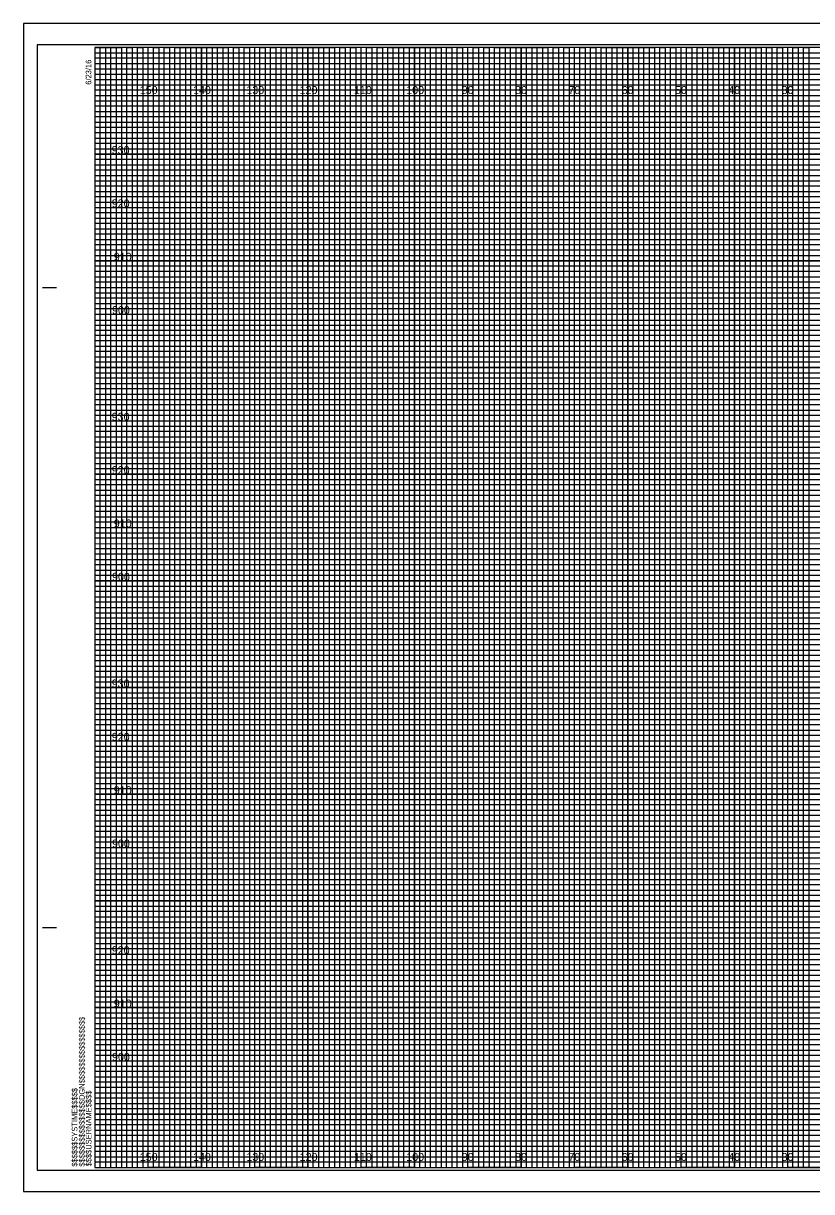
# Model space of a CAD drawing. Extents: x -13 to 323, y -4 to 3074.
# Drawn here: x -13.4 to 134.5, y -4.5 to 214.5 of the extents above; entities that cross this region are included whole.
import ezdxf

# ---------------------------------------------------------------- set-up
doc = ezdxf.new("R2010")
doc.units = 0
for name, color, linetype in [('Prop XS Elevation Labels', 7, 'Continuous'), ('Prop XS Offset Labels', 7, 'Continuous'), ('Sheet Cross Section CELL', 7, 'Continuous'), ('Sheet Cross Section Grid Major CELL', 7, 'Continuous'), ('Sheet Cross Section Grid Middle CELL', 7, 'Continuous'), ('Sheet Cross Section Grid Minor 1 CELL', 7, 'Continuous'), ('Sheet Cross Section Grid Minor 2 CELL', 7, 'Continuous'), ('Sheet Cutting Line CELL', 7, 'Continuous'), ('Sheet DOT Grid CELL', 7, 'Continuous'), ('Sheet Plot Border Inside CELL', 7, 'Continuous'), ('Sheet Plot Border Outside CELL', 7, 'Continuous')]:
    doc.layers.add(name, color=color, linetype=linetype)

msp = doc.modelspace()

# ---------------------------------------------------------------- linework, layer by layer
at = {"layer": 'Sheet Cross Section CELL'}
for p, q in [((-9.8, 165), (-7.3, 165)), ((-9.7, 165), (-7.2, 165)), ((-9.8, 45), (-7.3, 45)), ((-9.7, 45), (-7.2, 45)), ((0, 0), (0, 0)), ((0, 0), (0, 0)), ((0, 0), (0, 0)), ((0, 0), (0, 0)), ((0, 0), (0, 0)), ((0, 0), (0, 0)), ((0, 0), (0, 0))]:
    msp.add_line(p, q, dxfattribs=at)
msp.add_lwpolyline([(320, 210), (0, 210), (0, 0), (320, 0)], close=True, dxfattribs=at)
at = {"layer": 'Sheet Cross Section Grid Major CELL'}
for p, q in [((10, 210), (0, 210)), ((10, 0), (10, 210)), ((30, 210), (20, 210)), ((20, 210), (20, 0)), ((30, 0), (30, 210)), ((50, 210), (40, 210)), ((40, 210), (40, 0)), ((50, 0), (50, 210)), ((70, 210), (60, 210)), ((60, 210), (60, 0)), ((70, 0), (70, 210)), ((90, 210), (80, 210)), ((80, 210), (80, 0)), ((90, 0), (90, 210)), ((110, 210), (100, 210)), ((100, 210), (100, 0)), ((110, 0), (110, 210)), ((130, 210), (120, 210)), ((120, 210), (120, 0)), ((130, 0), (130, 210)), ((20, 0), (10, 0)), ((40, 0), (30, 0)), ((60, 0), (50, 0)), ((80, 0), (70, 0)), ((100, 0), (90, 0)), ((120, 0), (110, 0)), ((140, 0), (130, 0))]:
    msp.add_line(p, q, dxfattribs=at)
for points in [[(0, 200), (320, 200), (320, 190), (0, 190)], [(0, 180), (320, 180), (320, 170), (0, 170)], [(0, 160), (320, 160), (320, 150), (0, 150)], [(0, 140), (320, 140), (320, 130), (0, 130)], [(0, 120), (320, 120), (320, 110), (0, 110)], [(0, 100), (320, 100), (320, 90), (0, 90)], [(0, 80), (320, 80), (320, 70), (0, 70)], [(0, 60), (320, 60), (320, 50), (0, 50)], [(0, 40), (320, 40), (320, 30), (0, 30)], [(0, 20), (320, 20), (320, 10), (0, 10)]]:
    msp.add_lwpolyline(points, dxfattribs=at)
at = {"layer": 'Sheet Cross Section Grid Middle CELL'}
for points in [[(0, 210), (5, 210), (5, 0), (15, 0), (15, 210), (25, 210), (25, 0), (35, 0), (35, 210), (45, 210), (45, 0), (55, 0), (55, 210), (65, 210), (65, 0), (75, 0), (75, 210), (85, 210), (85, 0), (95, 0), (95, 210), (105, 210), (105, 0), (115, 0), (115, 210), (125, 210), (125, 0), (135, 0)], [(0, 205), (275, 205)], [(0, 185), (320, 185), (320, 195), (0, 195)], [(0, 165), (320, 165), (320, 175), (0, 175)], [(0, 145), (320, 145), (320, 155), (0, 155)], [(0, 125), (320, 125), (320, 135), (0, 135)], [(0, 105), (320, 105), (320, 115), (0, 115)], [(0, 85), (320, 85), (320, 95), (0, 95)], [(0, 65), (320, 65), (320, 75), (0, 75)], [(0, 45), (320, 45), (320, 55), (0, 55)], [(0, 25), (320, 25), (320, 35), (0, 35)], [(0, 5), (320, 5), (320, 15), (0, 15)]]:
    msp.add_lwpolyline(points, dxfattribs=at)
at = {"layer": 'Sheet Cross Section Grid Minor 1 CELL'}
for p, q in [((0, 209), (260, 209)), ((260, 207.98), (0, 207.98)), ((0, 207.98), (0, 207)), ((0, 207), (260, 207)), ((260, 205.89), (0, 205.89)), ((0, 205.89), (0, 204)), ((0, 204), (320, 204))]:
    msp.add_line(p, q, dxfattribs=at)
for points in [[(0, 203), (270, 203), (320, 203), (320, 202), (0, 202)], [(0, 201), (320, 201), (320, 199), (0, 199)], [(0, 198), (320, 198), (320, 197), (0, 196.98)], [(0, 196), (320, 196), (320, 194), (0, 194)], [(0, 193), (320, 193), (320, 192), (0, 192)], [(0, 191), (320, 191), (320, 189), (0, 189)], [(0, 188), (320, 188), (320, 187), (0, 187)], [(0, 186), (320, 186), (320, 184), (0, 184)], [(0, 183), (320, 183), (320, 182), (0, 182)], [(0, 181), (320, 181), (320, 179), (0, 179)], [(0, 178), (320, 178), (320, 177), (0, 177)], [(0, 176), (320, 176), (320, 173.95), (320, 173), (320, 172), (0, 172)], [(0, 174), (320, 174), (320, 173), (0, 173)], [(0, 171), (320, 171), (320, 169), (0, 169.03)], [(0, 169.03), (320, 169), (320, 168), (0, 168)], [(0, 167), (320, 167), (320, 166), (0, 166)], [(0, 164), (320, 164), (320, 163), (0, 163)], [(0, 162), (320, 162), (320, 161), (0, 161)], [(-0.07, 158.89), (320, 158.89), (320, 157.88), (-0.07, 157.88)], [(0, 157), (320, 157), (320, 156), (0, 156)], [(0, 154), (320, 154), (320, 153), (0, 153)], [(0, 152), (320, 152), (320, 151), (0, 151)], [(0, 149), (320, 149), (320, 148), (0, 148)], [(0, 147), (320, 147), (320, 146), (0, 146)], [(0, 144), (320, 144), (320, 143), (0, 143)], [(0, 142), (320, 142), (320, 141), (0, 141)], [(0, 139), (320, 139), (319.99, 137.98), (0, 138)], [(0, 137), (320, 137), (320, 136), (0, 136)], [(0, 134), (320, 134), (320, 133), (0, 133)], [(0, 132), (320, 132), (320, 131), (0, 131)], [(0, 129), (320, 129), (320, 128), (0, 128)], [(0, 127), (320, 127), (320, 126), (0, 126)], [(0, 124), (320, 124), (320, 123), (0, 123)], [(0, 122), (320, 122), (320, 121), (0, 121)], [(0, 119), (320, 119), (320, 118), (0, 118)], [(0, 116.99), (320.07, 116.91), (320, 116), (0, 116)], [(0, 114), (320, 114), (320, 113), (0, 113)], [(0, 112), (320, 112), (320, 111), (0, 111)], [(0, 109), (320, 109), (320, 108), (0, 108)], [(0, 107), (320, 107), (320, 106), (0, 106)], [(0, 104), (320, 104), (320, 103), (0, 103)], [(0, 102), (320, 102), (320, 101), (0, 101)], [(0, 99), (320, 99), (320, 98), (0, 98)], [(0, 97), (320, 97), (320, 96), (0, 96)], [(0, 94), (320, 94), (320, 93), (0, 93)], [(0, 92), (320, 92), (320, 91), (0, 91)], [(0, 89), (320, 89), (320, 88), (0, 88)], [(0, 87), (320, 87), (320, 86), (0, 86)], [(0, 84), (320, 84), (320, 83), (0, 83)], [(0, 82), (320, 82), (320, 81), (0, 81)], [(0, 79), (320, 79), (319.99, 77.98), (0, 78)], [(0, 77), (320, 77), (320, 76), (0, 76)], [(0, 74), (320, 74), (320, 73), (0, 73)], [(0, 72), (320, 72), (320, 71), (0, 71)], [(0, 69), (320, 69), (320, 68), (0, 68)], [(0, 67), (320, 67), (320, 66), (0, 66)], [(0, 64), (320, 64), (320, 63), (0, 63)], [(0, 62), (320, 62), (320, 61), (0, 61)], [(0, 59), (320, 59), (320, 58), (0, 58)], [(0, 56.99), (320.07, 56.91), (320, 56), (0, 56)], [(0, 54), (320, 54), (320, 53), (0, 53)], [(0, 52), (320, 52), (320, 51), (0, 51)], [(0, 49), (320, 49), (320, 48), (0, 48)], [(0, 47), (320, 47), (320, 46), (0, 46)], [(0, 44), (320, 44), (320, 43), (0, 43)], [(0, 42), (320, 42), (320, 41), (0, 41)], [(0, 39), (320, 39), (320, 38), (0, 38)], [(0, 37), (320, 37), (320, 36), (0, 36)], [(0, 34), (320, 34), (320, 33), (0, 33)], [(0, 32), (320, 32), (320, 31), (0, 31)], [(0, 29), (320, 29), (320, 28), (0, 28)], [(0, 27), (320, 27), (320, 26), (0, 26)], [(0, 24), (320, 24), (320, 23), (0, 23)], [(0, 22), (320, 22), (320, 21), (0, 21)], [(0, 19), (320, 19), (320, 18), (0, 18)], [(0, 17), (320, 17), (320, 16), (0, 16)], [(0, 14), (320, 14), (320, 13), (0, 13)], [(0, 12), (320, 12), (320, 11), (0, 11)], [(0, 9), (320, 9), (320, 8), (0, 8)], [(0, 7), (320, 7), (320, 6), (0, 6)], [(0, 4), (320, 4), (320, 3), (0, 3)], [(0, 2), (320, 2), (320, 1), (0, 1)]]:
    msp.add_lwpolyline(points, dxfattribs=at)
at = {"layer": 'Sheet Cross Section Grid Minor 2 CELL'}
for points in [[(0, 0), (1, 0), (1, 210), (2, 210), (2, 0)], [(2, 0), (3, 0), (3, 210), (4, 210), (4, 0)], [(5, 0), (6, 0), (6, 210), (7, 210), (7, 0)], [(7, 0), (8, 0), (8, 210), (9, 210), (9, 0)], [(10, 0), (11, 0), (11, 210), (12, 210), (12, 0)], [(12, 0), (13, 0), (13, 210), (14, 210), (14, 0)], [(15, 0), (16, 0), (16, 210), (17, 210), (17, 0)], [(17, 0), (18, 0), (18, 210), (19, 210), (19, 0)], [(20, 0), (21, 0), (21, 210), (22, 210), (22, 0)], [(22, 0), (23, 0), (23, 210), (24, 210), (24, 0)], [(25, 0), (26, 0), (26, 210), (27, 210), (27, 0)], [(27, 0), (28, 0), (28, 210), (29, 210), (29, 0)], [(30, 0), (31, 0), (31, 210), (32, 210), (32, 0)], [(32, 0), (33, 0), (33, 210), (34, 210), (34, 0)], [(35, 0), (36, 0), (36, 210), (37, 210), (37, 0)], [(37, 0), (38, 0), (38, 210), (39, 210), (39, 0)], [(40, 0), (41, 0), (41, 210), (42, 210), (42, 0)], [(42, 0), (43, 0), (43, 210), (44, 210), (44, 0)], [(45, 0), (46, 0), (46, 210), (47, 210), (47, 0)], [(47, 0), (48, 0), (48, 210), (49, 210), (49, 0)], [(50, 0), (51, 0), (51, 210), (52, 210), (52, 0)], [(52, 0), (53, 0), (53, 210), (54, 210), (54, 0)], [(55, 0), (56, 0), (56, 210), (57, 210), (57, 0)], [(57, 0), (58, 0), (58, 210), (59, 210), (59, 0)], [(60, 0), (61, 0), (61, 210), (62, 210), (62, 0)], [(62, 0), (63, 0), (63, 210), (64, 210), (64, 0)], [(65, 0), (66, 0), (66, 210), (67, 210), (67, 0)], [(67, 0), (68, 0), (68, 210), (69, 210), (69, 0)], [(70, 0), (71, 0), (71, 210), (72, 210), (72, 0)], [(72, 0), (73, 0), (73, 210), (74, 210), (74, 0)], [(75, 0), (76, 0), (76, 210), (77, 210), (77, 0)], [(77, 0), (78, 0), (78, 210), (79, 210), (79, 0)], [(80, 0), (81, 0), (81, 210), (82, 210), (82, 0)], [(82, 0), (83, 0), (83, 210), (84, 210), (84, 0)], [(85, 0), (86, 0), (86, 210), (87, 210), (87, 0)], [(87, 0), (88, 0), (88, 210), (89, 210), (89, 0)], [(90, 0), (91, 0), (91, 210), (92, 210), (92, 0)], [(92, 0), (93, 0), (93, 210), (94, 210), (94, 0)], [(95, 0), (96, 0), (96, 210), (97, 210), (97, 0)], [(97, 0), (98, 0), (98, 210), (99, 210), (99, 0)], [(100, 0), (101, 0), (101, 210), (102, 210), (102, 0)], [(102, 0), (103, 0), (103, 210), (104, 210), (104, 0)], [(105, 0), (106, 0), (106, 210), (107, 210), (107, 0)], [(107, 0), (108, 0), (108, 210), (109, 210), (109, 0)], [(110, 0), (111, 0), (111, 210), (112, 210), (112, 0)], [(112, 0), (113, 0), (113, 210), (114, 210), (114, 0)], [(115, 0), (116, 0), (116, 210), (117, 210), (117, 0)], [(117, 0), (118, 0), (118, 210), (119, 210), (119, 0)], [(120, 0), (121, 0), (121, 210), (122, 210), (122, 0)], [(122, 0), (123, 0), (123, 210), (124, 210), (124, 0)], [(125, 0), (126, 0), (126, 210), (127, 210), (127, 0)], [(127, 0), (128, 0), (128, 210), (129, 210), (129, 0)], [(130, 0), (131, 0), (131, 210), (132, 210), (132, 0)], [(132, 0), (133, 0), (133, 210), (134, 210), (134, 0)]]:
    msp.add_lwpolyline(points, dxfattribs=at)
at = {"layer": 'Sheet Cutting Line CELL'}
for p, q in [((323.3, 214.5), (-13.4, 214.5)), ((-13.4, 214.5), (-13.4, -4.5)), ((-13.4, -4.5), (323.3, -4.5))]:
    msp.add_line(p, q, dxfattribs=at)
at = {"layer": 'Sheet DOT Grid CELL'}
for p, q in [((10, 0), (10, 210)), ((20, 0), (20, 210)), ((30, 0), (30, 210)), ((40, 0), (40, 210)), ((50, 0), (50, 210)), ((60, 0), (60, 210)), ((70, 0), (70, 210)), ((80, 0), (80, 210)), ((90, 0), (90, 210)), ((100, 0), (100, 210)), ((110, 0), (110, 210)), ((120, 0), (120, 210)), ((130, 0), (130, 210)), ((0, 200), (320, 200)), ((0, 190), (320, 190)), ((0, 180), (320, 180)), ((0, 170), (320, 170)), ((0, 160), (320, 160)), ((0, 150), (320, 150)), ((0, 140), (320, 140)), ((0, 130), (320, 130)), ((0, 120), (320, 120)), ((0, 110), (320, 110)), ((0, 100), (320, 100)), ((0, 90), (320, 90)), ((0, 80), (320, 80)), ((0, 70), (320, 70)), ((0, 60), (320, 60)), ((0, 50), (320, 50)), ((0, 40), (320, 40)), ((0, 30), (320, 30)), ((0, 20), (320, 20)), ((0, 10), (320, 10))]:
    msp.add_line(p, q, dxfattribs=at)
at = {"layer": 'Sheet Plot Border Inside CELL'}
msp.add_lwpolyline([(-10.8, -0.5), (322.4, -0.5), (322.4, 210.5), (-10.8, 210.5)], close=True, dxfattribs=at)
at = {"layer": 'Sheet Plot Border Outside CELL'}
msp.add_lwpolyline([(-13.4, -4.5), (323.3, -4.5), (323.3, 214.5), (-13.4, 214.5)], close=True, dxfattribs=at)

# ---------------------------------------------------------------- texts
at = {"layer": 'Prop XS Elevation Labels'}
for s, p in [('930', (3.18, 190)), ('920', (3.19, 180)), ('910', (3.57, 170)), ('900', (3.24, 160)), ('930', (3.18, 140)), ('920', (3.19, 130)), ('910', (3.57, 120)), ('900', (3.24, 110)), ('930', (3.18, 90)), ('920', (3.19, 80)), ('910', (3.57, 70)), ('900', (3.24, 60)), ('920', (3.19, 40)), ('910', (3.57, 30)), ('900', (3.24, 20))]:
    msp.add_text(s, height=1.5, dxfattribs=at).set_placement(p)
at = {"layer": 'Prop XS Offset Labels'}
for s, p in [('150', (8.44, 201.25)), ('140', (18.44, 201.25)), ('130', (28.44, 201.25)), ('120', (38.44, 201.25)), ('110', (48.62, 201.25)), ('100', (58.44, 201.25)), ('90', (68.86, 201.25)), ('80', (78.86, 201.25)), ('70', (88.86, 201.25)), ('60', (98.86, 201.25)), ('50', (108.86, 201.25)), ('40', (118.86, 201.25)), ('30', (128.86, 201.25)), ('150', (8.44, 1.25)), ('140', (18.44, 1.25)), ('130', (28.44, 1.25)), ('120', (38.44, 1.25)), ('110', (48.62, 1.25)), ('100', (58.44, 1.25)), ('90', (68.86, 1.25)), ('80', (78.86, 1.25)), ('70', (88.86, 1.25)), ('60', (98.86, 1.25)), ('50', (108.86, 1.25)), ('40', (118.86, 1.25)), ('30', (128.86, 1.25))]:
    msp.add_text(s, height=1.5, dxfattribs=at).set_placement(p)
at = {"layer": 'Sheet Cross Section CELL'}
for s, p in [('6/23/16', (-0.65, 203)), ('$$$$$$$$$$$$$$$$DGN$$$$$$$$$$$$$$$$', (-1.88, 0.18)), ('$$$$$$SYSTIME$$$$$', (-3.26, 0.18)), ('$$$$USERNAME$$$$', (-0.62, 0.23))]:
    msp.add_text(s, height=1.05, rotation=90, dxfattribs=at).set_placement(p)

doc.saveas('drawing.dxf')
